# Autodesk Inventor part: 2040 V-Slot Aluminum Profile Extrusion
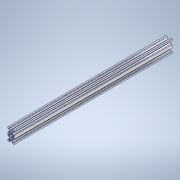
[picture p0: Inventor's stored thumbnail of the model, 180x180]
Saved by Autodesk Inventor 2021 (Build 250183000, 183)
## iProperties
Created: 2025-12
Part Number: 2040 V-Slot Aluminum Profile Extrusion
Material: Generic
Description: STEP AP214
Document SubType Name: Modeling
Designer: hp
Density: 1 g/cm^3
Appearance: Default
Sending System: SolidWorks 2024
Preprocessor: SwSTEP 2.0
Title: Aluminium profile 2040 500mm.STEP
Revision Number: ANY
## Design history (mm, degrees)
node "Cut-Extrude1"
body "Solid1"
